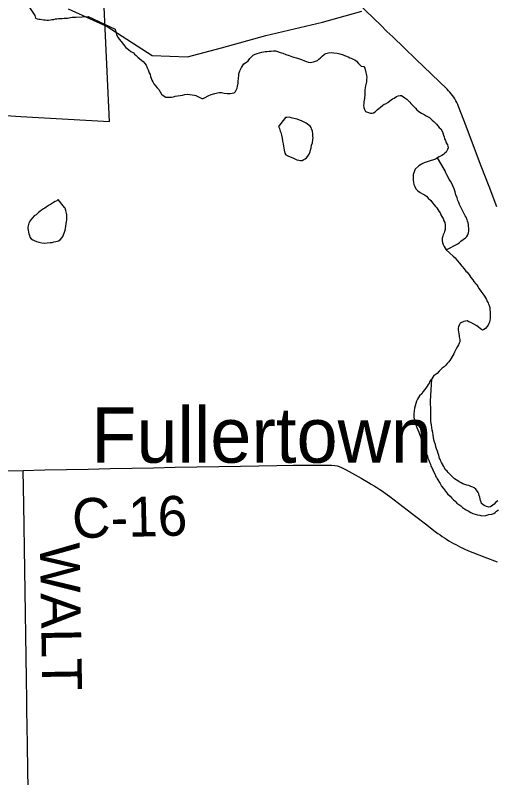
# Model space of a CAD drawing. Extents: x -11.4 to 84.1, y 11.1 to 59.
# Drawn here: x 29.827 to 30.516, y 45.542 to 46.631 of the extents above; entities that cross this region are included whole.
import ezdxf

# ---------------------------------------------------------------- set-up
doc = ezdxf.new("R2010")
doc.units = 0
for name, color, linetype in [('GM_X_Corporation', 7, 'Continuous'), ('GM_X_County_Road', 7, 'Continuous'), ('GM_X_County_Road_Text', 7, 'Continuous'), ('GM_X_Major_River', 7, 'Continuous'), ('GM_X_Minor_Lake', 7, 'Continuous'), ('GM_X_Rail_Line', 7, 'Continuous'), ('GM_X_Township_Road', 7, 'Continuous'), ('GM_X_Township_Road_Text', 7, 'Continuous'), ('GM_X_Unincorporated_Text', 7, 'Continuous')]:
    doc.layers.add(name, color=color, linetype=linetype)

msp = doc.modelspace()

# ---------------------------------------------------------------- linework, layer by layer
at = {"layer": 'GM_X_Corporation'}
msp.add_lwpolyline([(29.2807, 46.4633), (29.4869, 46.4478), (29.4834, 46.3883), (29.6985, 46.3706), (29.7063, 46.4947), (29.8352, 46.4859), (29.9622, 46.4788), (29.9464, 46.816), (29.9432, 46.8688), (29.9372, 46.8931), (29.8985, 46.896), (29.9001, 46.9199), (29.5467, 46.9424), (29.5434, 46.8903), (29.5061, 46.8927), (29.5056, 46.8842), (29.4682, 46.8866), (29.4704, 46.9206), (29.4238, 46.9236), (29.4228, 46.908), (29.2952, 46.9163)], dxfattribs=at)
at = {"layer": 'GM_X_County_Road'}
msp.add_line((30.3498, 46.6162), (30.3395, 46.6262), dxfattribs=at)
for points in [[(30.3395, 46.6262), (30.3172, 46.6478), (30.2994, 46.665), (30.2816, 46.6823), (30.2675, 46.6959), (30.2533, 46.7096), (30.2308, 46.7311), (30.2083, 46.7525), (30.1928, 46.7673), (30.1772, 46.7822), (30.1586, 46.7998), (30.14, 46.8174), (30.1177, 46.8391), (30.0993, 46.8569), (30.0809, 46.8748), (30.0672, 46.8878), (30.0535, 46.9008), (30.0412, 46.9126), (30.0289, 46.9243), (30.0181, 46.9349)], [(30.5157, 46.3571), (30.5046, 46.3862), (30.4935, 46.4152), (30.4825, 46.4442), (30.4717, 46.4723), (30.461, 46.5003), (30.4599, 46.5031), (30.4586, 46.5058), (30.4573, 46.5085), (30.4558, 46.5111), (30.4542, 46.5136), (30.4525, 46.516), (30.4506, 46.5184), (30.4487, 46.5207), (30.4468, 46.5229), (30.4446, 46.525), (30.4222, 46.5465), (30.3998, 46.5681), (30.3834, 46.5839), (30.3669, 46.5998), (30.3587, 46.6076), (30.3498, 46.6162)], [(29.8151, 45.9802), (29.8386, 45.9808), (29.8697, 45.9814), (29.9008, 45.9821), (29.9318, 45.9827), (29.9629, 45.9833), (29.994, 45.9839), (30.025, 45.9845), (30.0561, 45.9851), (30.0871, 45.9857), (30.1182, 45.9863), (30.1493, 45.9869), (30.1753, 45.9874), (30.2013, 45.9879), (30.2248, 45.9882), (30.2483, 45.9884), (30.264, 45.9883), (30.2796, 45.9882), (30.2842, 45.9877), (30.2873, 45.9873), (30.2904, 45.9862), (30.2936, 45.985), (30.2966, 45.9836), (30.3003, 45.9816), (30.3216, 45.9695), (30.3323, 45.9635), (30.3363, 45.9611), (30.3404, 45.9586), (30.3444, 45.9561), (30.3484, 45.9535), (30.3523, 45.9509), (30.3562, 45.9481), (30.3626, 45.9434), (30.3813, 45.9292), (30.3999, 45.9149), (30.4139, 45.9043), (30.4278, 45.8936), (30.4315, 45.8908), (30.4346, 45.8886), (30.4377, 45.8865), (30.4409, 45.8844), (30.444, 45.8823), (30.4473, 45.8803), (30.4505, 45.8784), (30.4538, 45.8765), (30.4572, 45.8747), (30.4605, 45.8729), (30.4639, 45.8712), (30.4673, 45.8696), (30.4708, 45.868), (30.4743, 45.8665), (30.4778, 45.865), (30.4813, 45.8636), (30.4987, 45.8569), (30.5162, 45.8501)]]:
    msp.add_lwpolyline(points, dxfattribs=at)
at = {"layer": 'GM_X_Major_River'}
for points in [[(29.8468, 46.6432), (29.8553, 46.6301)], [(29.8553, 46.6301), (29.8563, 46.6265), (29.8586, 46.6254), (29.8609, 46.625), (29.8631, 46.625), (29.8654, 46.6243), (29.8677, 46.6239), (29.8699, 46.6239), (29.8726, 46.6235), (29.8749, 46.6235), (29.8775, 46.6239), (29.8798, 46.6243), (29.8824, 46.6246), (29.8847, 46.6254), (29.887, 46.6254), (29.8892, 46.6258), (29.8942, 46.6258), (29.8972, 46.6262), (29.8998, 46.6265), (29.9021, 46.6265), (29.9089, 46.6277), (29.9116, 46.6277), (29.9142, 46.628), (29.9314, 46.6286)], [(29.9314, 46.6286), (29.9701, 46.6108), (29.9706, 46.6082), (29.9714, 46.6055), (29.9722, 46.6025), (29.9738, 46.5995), (29.9761, 46.5965), (29.9788, 46.5931), (29.9819, 46.589), (29.9854, 46.5845), (29.9892, 46.5819), (29.9927, 46.5789), (29.9962, 46.577), (29.9977, 46.5752), (30.0004, 46.5733), (30.0027, 46.5707), (30.0054, 46.5685), (30.0081, 46.5662), (30.0104, 46.5644), (30.0124, 46.5617), (30.0143, 46.5591), (30.0159, 46.5557), (30.0175, 46.5527), (30.019, 46.5485), (30.0202, 46.5459), (30.0206, 46.5432), (30.0215, 46.5406), (30.0226, 46.5379), (30.0238, 46.5353), (30.0254, 46.5327), (30.0277, 46.53), (30.0304, 46.527), (30.0324, 46.5244), (30.0343, 46.5214), (30.0363, 46.518), (30.0386, 46.5158), (30.0424, 46.5135), (30.0455, 46.5136), (30.0485, 46.5136), (30.0508, 46.5137), (30.0534, 46.5141), (30.0561, 46.5149), (30.0595, 46.5153), (30.0633, 46.5158), (30.0663, 46.5166), (30.0697, 46.5174), (30.0739, 46.5179), (30.0769, 46.5175), (30.08, 46.5172), (30.0834, 46.5165), (30.0857, 46.5158), (30.0891, 46.5139), (30.091, 46.5132), (30.0941, 46.5117), (30.096, 46.5118), (30.099, 46.513), (30.1032, 46.5153), (30.1073, 46.5173), (30.1126, 46.5189), (30.1164, 46.5197), (30.1186, 46.5201), (30.1221, 46.5202), (30.1259, 46.5195), (30.1301, 46.5188), (30.1346, 46.5189), (30.1376, 46.5193), (30.1403, 46.5197), (30.1422, 46.5216), (30.1433, 46.5236), (30.1444, 46.5266), (30.1451, 46.5293), (30.1458, 46.5335), (30.1461, 46.5369), (30.1464, 46.5396), (30.1464, 46.5415), (30.1467, 46.5438), (30.1471, 46.5468), (30.1485, 46.551), (30.1507, 46.556), (30.154, 46.561), (30.1578, 46.5637), (30.1604, 46.5657), (30.1626, 46.5688), (30.1656, 46.5718), (30.1675, 46.5734), (30.1701, 46.575), (30.1732, 46.5762), (30.1766, 46.577), (30.18, 46.5778), (30.1845, 46.5786), (30.1872, 46.579), (30.1902, 46.5795), (30.1932, 46.5795), (30.1963, 46.5796), (30.1993, 46.5796), (30.2023, 46.5789), (30.2058, 46.5774), (30.21, 46.5764), (30.2142, 46.5745), (30.2188, 46.5731), (30.2237, 46.5713)], [(30.2237, 46.5713), (30.2306, 46.5691), (30.2363, 46.5673), (30.2409, 46.5655), (30.2436, 46.5644), (30.2459, 46.5637), (30.249, 46.5629), (30.2535, 46.5642), (30.2565, 46.565), (30.2592, 46.5662), (30.2614, 46.5681), (30.2636, 46.57), (30.2659, 46.572), (30.2693, 46.5751), (30.2711, 46.5759), (30.2749, 46.5771), (30.2787, 46.5775), (30.2829, 46.5768), (30.2875, 46.5765), (30.2913, 46.5754), (30.2959, 46.574), (30.2982, 46.5729), (30.3008, 46.5722), (30.3031, 46.5711), (30.3054, 46.57), (30.3073, 46.5692), (30.3104, 46.5678), (30.3127, 46.5667), (30.315, 46.5648), (30.3181, 46.5618), (30.322, 46.5581), (30.3254, 46.5574), (30.3269, 46.5551), (30.3286, 46.549), (30.329, 46.5468), (30.3294, 46.5445), (30.3298, 46.5418), (30.3295, 46.5388), (30.3292, 46.5354), (30.3281, 46.5296), (30.3271, 46.5239), (30.3268, 46.5178), (30.3265, 46.5117), (30.3258, 46.5072), (30.3255, 46.5045), (30.3252, 46.5018), (30.3256, 46.4988), (30.3264, 46.4962), (30.328, 46.4931), (30.3322, 46.4917), (30.3352, 46.491), (30.3375, 46.491), (30.3394, 46.4914), (30.3417, 46.4926), (30.345, 46.4961), (30.3469, 46.4976), (30.3495, 46.4992), (30.3521, 46.5019), (30.3548, 46.5035), (30.3567, 46.5043), (30.3597, 46.5062), (30.3627, 46.5085), (30.3645, 46.5097), (30.3668, 46.5113), (30.3691, 46.5124), (30.3721, 46.5148), (30.3747, 46.5156), (30.3774, 46.516), (30.3796, 46.516), (30.3842, 46.5127), (30.3869, 46.5108), (30.3892, 46.509), (30.3912, 46.5067), (30.3927, 46.5048), (30.3958, 46.5015), (30.3974, 46.4996), (30.3993, 46.4977), (30.4016, 46.4955), (30.4043, 46.4932), (30.4078, 46.4906), (30.412, 46.4888), (30.4147, 46.487), (30.4174, 46.4855), (30.4193, 46.4844), (30.4212, 46.4829), (30.4231, 46.481), (30.4255, 46.4788), (30.4274, 46.4769), (30.4293, 46.475), (30.4312, 46.4728), (30.4332, 46.4705), (30.4355, 46.4683), (30.4378, 46.4649), (30.4386, 46.4626), (30.4394, 46.4596), (30.4402, 46.457), (30.4411, 46.4543), (30.4422, 46.4517), (30.4434, 46.4483), (30.445, 46.4456), (30.4458, 46.4437)], [(30.4458, 46.4437), (30.4462, 46.4411), (30.4451, 46.4388), (30.4433, 46.4353), (30.4414, 46.4338), (30.4395, 46.4318), (30.4373, 46.4303), (30.4335, 46.4283), (30.4308, 46.4268)], [(30.4308, 46.4268), (30.4279, 46.4252), (30.4177, 46.4216), (30.412, 46.42), (30.4079, 46.418), (30.4041, 46.4157), (30.3989, 46.4106), (30.3981, 46.4083), (30.3971, 46.4057), (30.3963, 46.403), (30.396, 46.4011), (30.396, 46.3984), (30.3961, 46.3954), (30.3965, 46.392), (30.3973, 46.3889), (30.3985, 46.3863), (30.4001, 46.3829), (30.4028, 46.3799), (30.4059, 46.3777), (30.4093, 46.3758), (30.4124, 46.374), (30.4151, 46.3721), (30.4178, 46.3695), (30.4213, 46.3661), (30.4236, 46.3628), (30.4263, 46.3598), (30.4282, 46.3575), (30.4298, 46.3556), (30.4313, 46.3534), (30.4329, 46.3507), (30.4345, 46.3485), (30.4357, 46.3458), (30.4372, 46.3432), (30.4388, 46.3406), (30.44, 46.3372), (30.4412, 46.3349), (30.442, 46.3315), (30.442, 46.3288), (30.442, 46.3269), (30.4417, 46.3246), (30.441, 46.3216), (30.4403, 46.3197), (30.4392, 46.317), (30.4384, 46.3151), (30.4377, 46.3124), (30.4378, 46.3105), (30.4378, 46.3086), (30.4382, 46.3063), (30.439, 46.3033), (30.4402, 46.3003), (30.4418, 46.298), (30.4433, 46.2958), (30.4435, 46.2956)], [(30.4435, 46.2956), (30.4599, 46.3044), (30.4618, 46.3056), (30.4644, 46.3079), (30.4674, 46.3102), (30.4708, 46.313), (30.4726, 46.3149), (30.4741, 46.3172), (30.4752, 46.3199), (30.4759, 46.3229), (30.4759, 46.3263), (30.4754, 46.3298), (30.475, 46.332), (30.4746, 46.3343), (30.4738, 46.3366), (30.4734, 46.3385), (30.4718, 46.3423), (30.4706, 46.3441), (30.4695, 46.346), (30.4679, 46.349), (30.4636, 46.3573), (30.4624, 46.3603), (30.4612, 46.363), (30.46, 46.366), (30.4588, 46.3698), (30.4572, 46.374), (30.456, 46.3785), (30.4548, 46.3827), (30.4528, 46.3868), (30.4512, 46.3902), (30.4493, 46.3936), (30.4477, 46.3962), (30.4462, 46.3993), (30.4442, 46.4026), (30.443, 46.4057), (30.4418, 46.4083), (30.4403, 46.4106), (30.4308, 46.4268)], [(30.4435, 46.2956), (30.4534, 46.2868), (30.4561, 46.2842), (30.4592, 46.2804), (30.4623, 46.2767), (30.4658, 46.2722), (30.4689, 46.2684), (30.4716, 46.2654), (30.4735, 46.2636), (30.4754, 46.2613), (30.477, 46.2587), (30.4786, 46.256), (30.4813, 46.2527), (30.4828, 46.2504), (30.4852, 46.2478), (30.4871, 46.2455), (30.4886, 46.2433), (30.4906, 46.2399), (30.4929, 46.2365), (30.4957, 46.2327), (30.498, 46.2297), (30.4996, 46.2271), (30.5011, 46.2245), (30.5019, 46.2218), (30.5031, 46.2199), (30.5039, 46.2181), (30.5047, 46.2162), (30.5055, 46.2131), (30.5059, 46.2101), (30.5063, 46.2071), (30.5064, 46.204), (30.5061, 46.2014), (30.5061, 46.1991), (30.5061, 46.1972), (30.5058, 46.1953), (30.5051, 46.1926), (30.5043, 46.1903), (30.5032, 46.188), (30.5014, 46.1857), (30.4995, 46.1834), (30.4973, 46.1818), (30.4954, 46.181), (30.4923, 46.1829)], [(30.4923, 46.1829), (30.4892, 46.1855), (30.4869, 46.187), (30.4785, 46.1918), (30.4758, 46.1929), (30.4731, 46.1944), (30.4686, 46.1931), (30.4633, 46.1911), (30.4622, 46.1892), (30.4607, 46.1858), (30.4604, 46.1839), (30.4604, 46.1812), (30.4609, 46.1786), (30.4613, 46.1755), (30.4617, 46.1733), (30.4621, 46.1714), (30.4622, 46.1695), (30.4626, 46.1676), (30.4626, 46.1645), (30.4619, 46.1626), (30.4608, 46.1599), (30.4593, 46.1576), (30.4575, 46.1545), (30.4564, 46.1522), (30.4553, 46.1496), (30.4542, 46.1473), (30.4527, 46.1446), (30.4516, 46.1423), (30.4501, 46.14), (30.4483, 46.1377), (30.4468, 46.1354), (30.4445, 46.1334), (30.4427, 46.1311), (30.4404, 46.1284), (30.4378, 46.1265), (30.4352, 46.1245), (30.4333, 46.1222), (30.4303, 46.1191), (30.4277, 46.1172), (30.4258, 46.116), (30.424, 46.1137), (30.4227, 46.1116)], [(30.4227, 46.1116), (30.4214, 46.1098), (30.4195, 46.1072), (30.4188, 46.1052), (30.4177, 46.1033), (30.4162, 46.101), (30.4144, 46.0983), (30.4125, 46.0956), (30.4103, 46.0933), (30.4084, 46.0899), (30.4054, 46.0871), (30.4039, 46.0848), (30.4025, 46.0822), (30.401, 46.0795), (30.3999, 46.0764), (30.3988, 46.073), (30.3981, 46.0695), (30.3974, 46.0657), (30.3971, 46.0612), (30.3972, 46.057), (30.3976, 46.0539), (30.3984, 46.0513), (30.3992, 46.0486), (30.4, 46.0456), (30.4016, 46.0422), (30.4028, 46.0388), (30.404, 46.0354), (30.4052, 46.0324), (30.4064, 46.029), (30.4076, 46.0256), (30.4088, 46.0222), (30.41, 46.0184), (30.4108, 46.0135), (30.4128, 46.0097), (30.4136, 46.0067), (30.4152, 46.0036), (30.4164, 46.001), (30.4172, 45.9984), (30.4184, 45.9953), (30.4196, 45.9923), (30.4207, 45.9897), (30.4215, 45.987), (30.4227, 45.9848), (30.4243, 45.9817), (30.4259, 45.978), (30.4274, 45.975), (30.4282, 45.9727), (30.4294, 45.9708), (30.4306, 45.9685), (30.4345, 45.9618), (30.4368, 45.9584), (30.4395, 45.955), (30.4423, 45.9512), (30.445, 45.9471), (30.4489, 45.9437), (30.4512, 45.9411), (30.4539, 45.9385), (30.4562, 45.9366), (30.4585, 45.934), (30.4616, 45.9318)], [(30.5173, 45.9373), (30.5139, 45.9349), (30.5117, 45.9326), (30.5098, 45.9311), (30.5068, 45.9287), (30.5042, 45.9283), (30.5008, 45.929), (30.4977, 45.9305), (30.4938, 45.9335), (30.4931, 45.9353), (30.4926, 45.9376), (30.4918, 45.9403), (30.4914, 45.9425), (30.4906, 45.9448), (30.4898, 45.9471), (30.489, 45.9493), (30.4871, 45.952), (30.4859, 45.9539), (30.4832, 45.9557), (30.4813, 45.9568), (30.4786, 45.9579), (30.4759, 45.959), (30.4729, 45.9597), (30.4702, 45.9608), (30.4672, 45.9615), (30.4649, 45.963), (30.4618, 45.9645), (30.4599, 45.966), (30.4576, 45.9671), (30.4553, 45.9686), (30.4518, 45.9719), (30.4499, 45.9738), (30.4479, 45.9757), (30.446, 45.9775), (30.4448, 45.9794), (30.4421, 45.982), (30.441, 45.9843), (30.4398, 45.9862), (30.4367, 45.9918), (30.4359, 45.9937), (30.4351, 45.9956), (30.4339, 45.9979), (30.4335, 46.0001), (30.4327, 46.0024), (30.4319, 46.0047), (30.4307, 46.0081), (30.4295, 46.0115), (30.4287, 46.0145), (30.4279, 46.0175), (30.4267, 46.021), (30.4259, 46.0244), (30.425, 46.0278), (30.4246, 46.0312), (30.4242, 46.0346), (30.4233, 46.0384), (30.4229, 46.0418), (30.4221, 46.0456), (30.4216, 46.0505), (30.4216, 46.0543), (30.4215, 46.057), (30.4214, 46.0604), (30.4214, 46.0635), (30.4214, 46.0661), (30.4213, 46.0692), (30.4213, 46.0714), (30.4208, 46.0745), (30.4208, 46.0794), (30.4227, 46.1116)], [(30.4616, 45.9318), (30.4643, 45.9299), (30.4666, 45.9277), (30.4693, 45.9258), (30.472, 45.9243), (30.4746, 45.9229), (30.4785, 45.9207), (30.4815, 45.9192), (30.4846, 45.9181), (30.488, 45.9174), (30.4915, 45.9167), (30.4945, 45.916), (30.5002, 45.9164), (30.5044, 45.9177), (30.5085, 45.9181), (30.5112, 45.9193), (30.5131, 45.9205), (30.5153, 45.9224), (30.5183, 45.9243)]]:
    msp.add_lwpolyline(points, dxfattribs=at)
at = {"layer": 'GM_X_Minor_Lake'}
for points in [[(30.2138, 46.4848), (30.2038, 46.4717), (30.205, 46.4687), (30.2062, 46.4653), (30.207, 46.463), (30.2078, 46.4592), (30.209, 46.4551), (30.2094, 46.4509), (30.2103, 46.4471), (30.2107, 46.4437), (30.2111, 46.4406), (30.2115, 46.438), (30.2128, 46.4338), (30.2143, 46.4312), (30.217, 46.4301), (30.2204, 46.4286), (30.2239, 46.4272), (30.2269, 46.4257), (30.23, 46.4242), (30.2327, 46.4235), (30.2353, 46.4232), (30.2376, 46.4232), (30.2399, 46.4244), (30.2418, 46.4256), (30.2436, 46.4271), (30.2455, 46.4294), (30.2473, 46.4321), (30.2484, 46.4344), (30.2495, 46.4379), (30.2502, 46.4413), (30.2509, 46.4451), (30.252, 46.4485), (30.2527, 46.4531), (30.253, 46.4558), (30.2526, 46.4581), (30.2526, 46.4615), (30.2521, 46.4649), (30.2509, 46.4683), (30.2501, 46.4702), (30.249, 46.4721), (30.247, 46.4736), (30.2432, 46.4765), (30.2401, 46.478), (30.2367, 46.4798), (30.2336, 46.4809), (30.2302, 46.482), (30.2256, 46.4831), (30.2218, 46.4842), (30.2195, 46.4849), (30.2157, 46.4848), (30.2138, 46.4848)], [(30.2138, 46.4848), (30.2038, 46.4717), (30.205, 46.4687), (30.2062, 46.4653), (30.207, 46.463), (30.2078, 46.4592), (30.209, 46.4551), (30.2094, 46.4509), (30.2103, 46.4471), (30.2107, 46.4437), (30.2111, 46.4406), (30.2115, 46.438), (30.2128, 46.4338), (30.2143, 46.4312), (30.217, 46.4301), (30.2204, 46.4286), (30.2239, 46.4272), (30.2269, 46.4257), (30.23, 46.4242), (30.2327, 46.4235), (30.2353, 46.4232), (30.2376, 46.4232), (30.2399, 46.4244), (30.2418, 46.4256), (30.2436, 46.4271), (30.2455, 46.4294)], [(30.2455, 46.4294), (30.2473, 46.4321), (30.2484, 46.4344), (30.2495, 46.4379), (30.2502, 46.4413), (30.2509, 46.4451), (30.252, 46.4485), (30.2527, 46.4531), (30.253, 46.4558), (30.2526, 46.4581), (30.2526, 46.4615), (30.2521, 46.4649), (30.2509, 46.4683), (30.2501, 46.4702), (30.249, 46.4721), (30.247, 46.4736), (30.2432, 46.4765), (30.2401, 46.478), (30.2367, 46.4798), (30.2336, 46.4809), (30.2302, 46.482), (30.2256, 46.4831), (30.2218, 46.4842), (30.2195, 46.4849), (30.2157, 46.4848), (30.2138, 46.4848)], [(29.8888, 46.3677), (29.8869, 46.3657), (29.8846, 46.3645), (29.882, 46.363), (29.8794, 46.3614), (29.8775, 46.3602), (29.8756, 46.3595), (29.8715, 46.3567), (29.8696, 46.3552), (29.8677, 46.3544), (29.8651, 46.3524), (29.8625, 46.3505), (29.8606, 46.3489), (29.8572, 46.3458), (29.8546, 46.3443), (29.852, 46.3412), (29.8498, 46.3385), (29.8483, 46.3366), (29.8468, 46.3335), (29.8461, 46.3316), (29.8454, 46.3282), (29.8454, 46.3259), (29.8458, 46.3236), (29.8463, 46.3209), (29.8467, 46.3183), (29.8475, 46.316), (29.8483, 46.3138), (29.8502, 46.3115), (29.8525, 46.31), (29.8544, 46.3089), (29.8575, 46.3074), (29.8609, 46.3067), (29.8655, 46.3057), (29.8685, 46.3053), (29.8773, 46.3059), (29.8799, 46.3063), (29.8826, 46.3071), (29.8852, 46.3075), (29.8875, 46.3079), (29.8894, 46.3087), (29.8916, 46.3099), (29.8942, 46.3134), (29.8957, 46.3157), (29.8968, 46.3184), (29.8979, 46.321), (29.8986, 46.3237), (29.899, 46.326), (29.9007, 46.3361)], [(29.8979, 46.3563), (29.8888, 46.3677)], [(29.9007, 46.3361), (29.901, 46.3382), (29.901, 46.3401), (29.901, 46.342), (29.9009, 46.3454), (29.9005, 46.3481), (29.9001, 46.35), (29.8997, 46.3519), (29.8985, 46.3553), (29.8979, 46.3563)]]:
    msp.add_lwpolyline(points, dxfattribs=at)
at = {"layer": 'GM_X_Rail_Line'}
msp.add_lwpolyline([(29.9029, 46.6398), (29.9588, 46.6144), (30.0232, 46.5733), (30.0738, 46.5712), (30.1223, 46.5839), (30.1856, 46.6018), (30.2666, 46.6209), (30.3227, 46.6366)], dxfattribs=at)
at = {"layer": 'GM_X_Township_Road'}
msp.add_line((30.3498, 46.6162), (30.3395, 46.6262), dxfattribs=at)
for points in [[(30.3395, 46.6262), (30.3172, 46.6478), (30.2994, 46.665), (30.2816, 46.6823), (30.2675, 46.6959), (30.2533, 46.7096), (30.2308, 46.7311), (30.2083, 46.7525), (30.1928, 46.7673), (30.1772, 46.7822), (30.1586, 46.7998), (30.14, 46.8174), (30.1177, 46.8391), (30.0993, 46.8569), (30.0809, 46.8748), (30.0672, 46.8878), (30.0535, 46.9008), (30.0412, 46.9126), (30.0289, 46.9243), (30.0181, 46.9349)], [(30.5157, 46.3571), (30.5046, 46.3862), (30.4935, 46.4152), (30.4825, 46.4442), (30.4717, 46.4723), (30.461, 46.5003), (30.4599, 46.5031), (30.4586, 46.5058), (30.4573, 46.5085), (30.4558, 46.5111), (30.4542, 46.5136), (30.4525, 46.516), (30.4506, 46.5184), (30.4487, 46.5207), (30.4468, 46.5229), (30.4446, 46.525), (30.4222, 46.5465), (30.3998, 46.5681), (30.3834, 46.5839), (30.3669, 46.5998), (30.3587, 46.6076), (30.3498, 46.6162)], [(29.8458, 45.5246), (29.8453, 45.5556), (29.8448, 45.5867), (29.8443, 45.6178), (29.844, 45.6351), (29.8438, 45.6524), (29.8433, 45.6835), (29.8428, 45.7145), (29.8423, 45.7456), (29.8418, 45.7767), (29.8414, 45.8077), (29.8409, 45.8388), (29.8404, 45.8699), (29.8399, 45.9009), (29.8394, 45.932), (29.839, 45.9564), (29.8386, 45.9808)]]:
    msp.add_lwpolyline(points, dxfattribs=at)

# ---------------------------------------------------------------- texts
at = {"layer": 'GM_X_County_Road_Text'}
msp.add_text('C-16', height=0.05682, rotation=1.3726, dxfattribs=at).set_placement((29.9092, 45.8839))
at = {"layer": 'GM_X_Township_Road_Text'}
msp.add_text('WALT', height=0.05682, rotation=270.9504, dxfattribs=at).set_placement((29.8626, 45.8771))
at = {"layer": 'GM_X_Unincorporated_Text'}
msp.add_text('Fullertown', height=0.07898, rotation=0, dxfattribs=at).set_placement((29.936, 45.9917))

doc.saveas('drawing.dxf')
